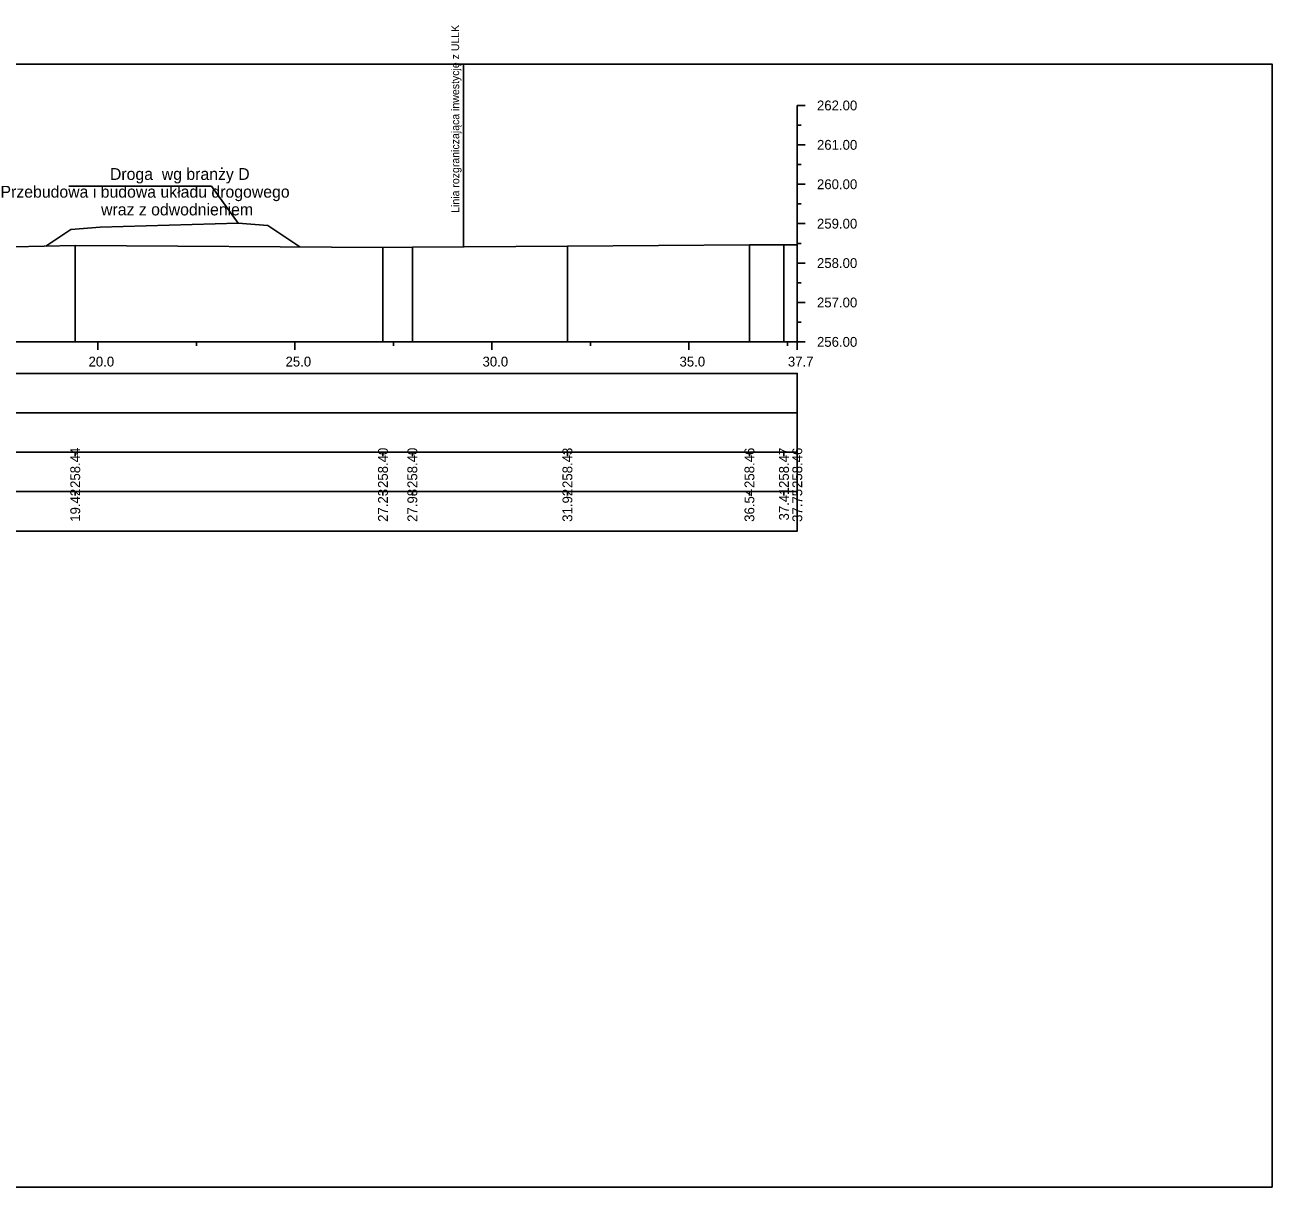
# Model space of a CAD drawing. Extents: x 6516023 to 6560129, y 5513077 to 5529206.
# Drawn here: x 6516577.86 to 6516609.51, y 5514451.16 to 5514480.65 of the extents above; entities that cross this region are included whole.
import ezdxf

# ---------------------------------------------------------------- set-up
doc = ezdxf.new("R2010")
doc.units = 0
for name, color, linetype in [('TOR_PRZEK_P-inne branze', 7, 'Continuous'), ('TOR_PRZEK_P-tabelka istniejace', 7, 'Continuous'), ('TOR_PRZEK_P-tabelka projektowane', 7, 'Continuous'), ('TOR_PRZEK_P-teren istniejacy', 7, 'Continuous'), ('TOR_PRZEK_P-uklad odniesienia', 7, 'Continuous'), ('TOR_PS_T-granica PKP-projektowana', 7, 'Continuous'), ('TOR_RAMKI-ramka+tabelka 1', 7, 'Continuous')]:
    doc.layers.add(name, color=color, linetype=linetype)

msp = doc.modelspace()

# ---------------------------------------------------------------- linework, layer by layer
at = {"layer": 'TOR_PRZEK_P-inne branze'}
for p, q in [((6516582.598, 5514476.556), (6516578.974, 5514476.556)), ((6516583.274, 5514475.622), (6516582.598, 5514476.556))]:
    msp.add_line(p, q, dxfattribs=at)
msp.add_lwpolyline([(6516578.39, 5514475.034), (6516579.024, 5514475.457), (6516579.774, 5514475.517), (6516581.524, 5514475.569), (6516583.274, 5514475.622), (6516584.024, 5514475.562), (6516584.84, 5514475.017)], dxfattribs=at)
at = {"layer": 'TOR_PRZEK_P-tabelka istniejace'}
for p, q in [((6516579.137, 5514469.706), (6516579.137, 5514469.806)), ((6516586.947, 5514469.706), (6516586.947, 5514469.806)), ((6516587.693, 5514469.706), (6516587.693, 5514469.806)), ((6516591.629, 5514469.706), (6516591.629, 5514469.806)), ((6516596.249, 5514469.706), (6516596.249, 5514469.806)), ((6516597.125, 5514469.706), (6516597.125, 5514469.806)), ((6516597.463, 5514469.706), (6516597.463, 5514469.806)), ((6516518.663, 5514468.806), (6516597.463, 5514468.806)), ((6516579.137, 5514468.706), (6516579.137, 5514468.806)), ((6516586.947, 5514468.706), (6516586.947, 5514468.806)), ((6516587.693, 5514468.706), (6516587.693, 5514468.806)), ((6516591.629, 5514468.706), (6516591.629, 5514468.806)), ((6516596.249, 5514468.706), (6516596.249, 5514468.806)), ((6516597.125, 5514468.706), (6516597.125, 5514468.806)), ((6516597.463, 5514468.706), (6516597.463, 5514468.806))]:
    msp.add_line(p, q, dxfattribs=at)
for points in [[(6516579.137, 5514475.05), (6516579.137, 5514472.806), (6516579.137, 5514472.676), (6516579.137, 5514472.606)], [(6516586.947, 5514475.005), (6516586.947, 5514472.806), (6516586.947, 5514472.676), (6516586.947, 5514472.606)], [(6516587.693, 5514475.008), (6516587.693, 5514472.806), (6516587.693, 5514472.676), (6516587.693, 5514472.606)], [(6516591.629, 5514475.034), (6516591.629, 5514472.806), (6516591.629, 5514472.676), (6516591.629, 5514472.606)], [(6516596.249, 5514475.068), (6516596.249, 5514472.806), (6516596.249, 5514472.676), (6516596.249, 5514472.606)], [(6516597.125, 5514475.071), (6516597.125, 5514472.806), (6516597.125, 5514472.676), (6516597.125, 5514472.606)], [(6516597.463, 5514475.069), (6516597.463, 5514472.806), (6516597.463, 5514472.676), (6516597.463, 5514472.606)]]:
    msp.add_lwpolyline(points, dxfattribs=at)
msp.add_lwpolyline([(6516518.663, 5514469.806), (6516518.663, 5514467.806), (6516597.463, 5514467.806), (6516597.463, 5514469.806)], close=True, dxfattribs=at)
at = {"layer": 'TOR_PRZEK_P-tabelka projektowane'}
msp.add_line((6516518.663, 5514470.806), (6516597.463, 5514470.806), dxfattribs=at)
msp.add_lwpolyline([(6516518.663, 5514471.806), (6516518.663, 5514469.806), (6516597.463, 5514469.806), (6516597.463, 5514471.806)], close=True, dxfattribs=at)
at = {"layer": 'TOR_PRZEK_P-teren istniejacy'}
msp.add_lwpolyline([(6516576.769, 5514475), (6516579.137, 5514475.05), (6516586.947, 5514475.005), (6516587.693, 5514475.008), (6516591.629, 5514475.034), (6516596.249, 5514475.068), (6516597.125, 5514475.071), (6516597.463, 5514475.069)], dxfattribs=at)
at = {"layer": 'TOR_PRZEK_P-uklad odniesienia'}
for p, q in [((6516597.463, 5514478.606), (6516597.463, 5514472.606)), ((6516597.663, 5514478.606), (6516597.463, 5514478.606)), ((6516597.563, 5514478.106), (6516597.463, 5514478.106)), ((6516597.663, 5514477.606), (6516597.463, 5514477.606)), ((6516597.563, 5514477.106), (6516597.463, 5514477.106)), ((6516597.663, 5514476.606), (6516597.463, 5514476.606)), ((6516597.563, 5514476.106), (6516597.463, 5514476.106)), ((6516597.663, 5514475.606), (6516597.463, 5514475.606)), ((6516597.563, 5514475.106), (6516597.463, 5514475.106)), ((6516597.663, 5514474.606), (6516597.463, 5514474.606)), ((6516597.563, 5514474.106), (6516597.463, 5514474.106)), ((6516597.663, 5514473.606), (6516597.463, 5514473.606)), ((6516597.563, 5514473.106), (6516597.463, 5514473.106)), ((6516522.463, 5514472.606), (6516597.463, 5514472.606)), ((6516579.713, 5514472.406), (6516579.713, 5514472.606)), ((6516582.213, 5514472.506), (6516582.213, 5514472.606)), ((6516584.713, 5514472.406), (6516584.713, 5514472.606)), ((6516587.213, 5514472.506), (6516587.213, 5514472.606)), ((6516589.713, 5514472.406), (6516589.713, 5514472.606)), ((6516592.213, 5514472.506), (6516592.213, 5514472.606)), ((6516594.713, 5514472.406), (6516594.713, 5514472.606)), ((6516597.213, 5514472.506), (6516597.213, 5514472.606)), ((6516597.463, 5514472.406), (6516597.463, 5514472.606)), ((6516597.663, 5514472.606), (6516597.463, 5514472.606))]:
    msp.add_line(p, q, dxfattribs=at)
at = {"layer": 'TOR_PS_T-granica PKP-projektowana'}
msp.add_line((6516588.994, 5514475.017), (6516588.994, 5514479.636), dxfattribs=at)
at = {"layer": 'TOR_RAMKI-ramka+tabelka 1'}
msp.add_lwpolyline([(6516362.013, 5514479.656), (6516609.513, 5514479.656), (6516609.513, 5514451.156), (6516362.013, 5514451.156)], close=True, dxfattribs=at)

# ---------------------------------------------------------------- texts
at = {"layer": 'TOR_PRZEK_P-inne branze'}
for s, p in [('Droga  wg branży D', (6516580.018, 5514476.716)), ('Przebudowa i budowa układu drogowego', (6516577.241, 5514476.266)), ('wraz z odwodnieniem ', (6516579.793, 5514475.816))]:
    msp.add_text(s, height=0.3, dxfattribs=at).set_placement(p)
at = {"layer": 'TOR_PRZEK_P-tabelka istniejace'}
for s, p in [('258.44', (6516579.262, 5514468.899)), ('258.40', (6516587.072, 5514468.898)), ('258.40', (6516587.818, 5514468.898)), ('258.43', (6516591.754, 5514468.898)), ('258.46', (6516596.374, 5514468.898)), ('258.47', (6516597.25, 5514468.898)), ('258.46', (6516597.588, 5514468.898)), ('19.42', (6516579.262, 5514468.04)), ('27.23', (6516587.072, 5514468.038)), ('27.98', (6516587.818, 5514468.038)), ('31.92', (6516591.754, 5514468.04)), ('36.54', (6516596.374, 5514468.039)), ('37.41', (6516597.25, 5514468.073)), ('37.75', (6516597.588, 5514468.037))]:
    msp.add_text(s, height=0.25, rotation=90, dxfattribs=at).set_placement(p)
at = {"layer": 'TOR_PRZEK_P-uklad odniesienia'}
for s, p in [('262.00', (6516597.963, 5514478.481)), ('261.00', (6516597.963, 5514477.481)), ('260.00', (6516597.963, 5514476.481)), ('259.00', (6516597.963, 5514475.481)), ('258.00', (6516597.963, 5514474.481)), ('257.00', (6516597.963, 5514473.481)), ('256.00', (6516597.963, 5514472.481)), ('20.0', (6516579.474, 5514471.981)), ('25.0', (6516584.474, 5514471.981)), ('30.0', (6516589.474, 5514471.981)), ('35.0', (6516594.474, 5514471.981)), ('37.7', (6516597.224, 5514471.981))]:
    msp.add_text(s, height=0.25, dxfattribs=at).set_placement(p)
at = {"layer": 'TOR_PS_T-granica PKP-projektowana'}
msp.add_text('Linia rozgraniczająca inwestycję z ULLK', height=0.2, rotation=90.0511, dxfattribs=at).set_placement((6516588.884, 5514475.881))

doc.saveas('drawing.dxf')
